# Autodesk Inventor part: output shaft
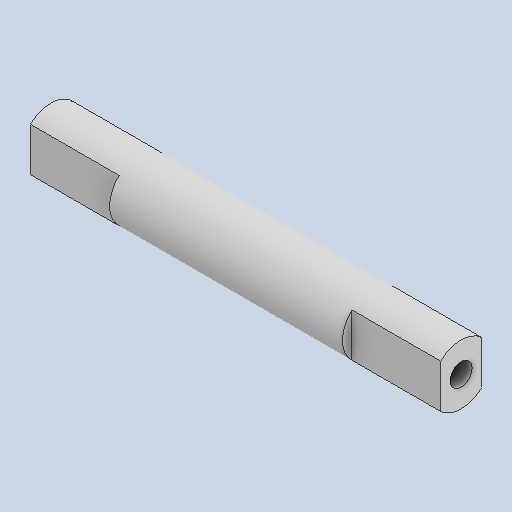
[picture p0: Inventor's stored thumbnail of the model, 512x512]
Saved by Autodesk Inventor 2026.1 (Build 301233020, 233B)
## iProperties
Created: 2019-04
Part Number: output shaft
Material: Generic
Document SubType Name: Modeling
Designer: hp
Density: 1 g/cm^3
Appearance: Default
Author: hp
Revision Number: ANY
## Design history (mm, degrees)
mirror "Mirror1"
body "Solid1"
